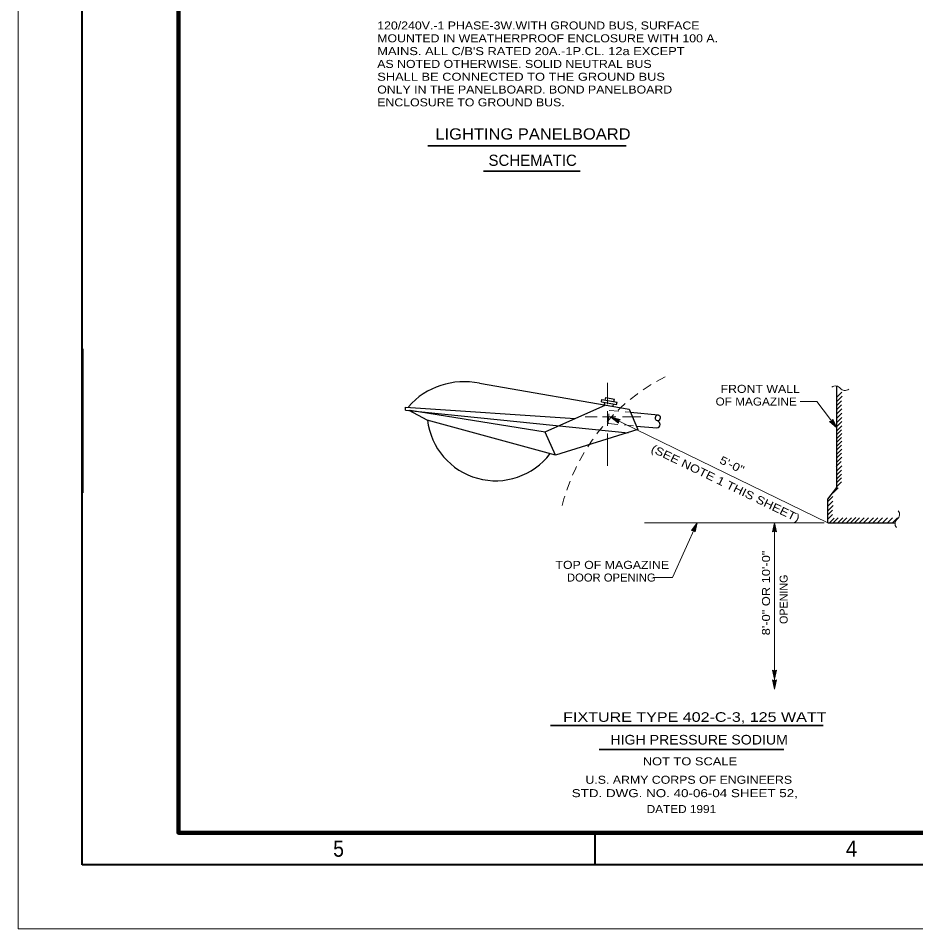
# Model space of a CAD drawing. Extents: x -39.6 to 16.1, y -17.6 to 34.
# Drawn here: x -25.9 to -11.89, y -17.59 to -3.38 of the extents above; entities that cross this region are included whole.
import ezdxf
from ezdxf.enums import TextEntityAlignment as Align

# ---------------------------------------------------------------- set-up
doc = ezdxf.new("R2010")
doc.units = 0
doc.header["$LTSCALE"] = 0.05
doc.linetypes.add('MEDIUM_DASHED', pattern=[4.5, 3, -1.5])
doc.layers.add('1', color=7, linetype='Continuous', lineweight=13)

msp = doc.modelspace()

# ---------------------------------------------------------------- linework, layer by layer
at = {"layer": '1'}
for p, q in [((-25.89821, -17.59158), (-25.89821, 12.40842)), ((-16.69821, -9.40258), (-16.69821, -9.06758)), ((-13.12121, -9.28958), (-13.04321, -9.21158)), ((-13.12321, -9.42758), (-13.04521, -9.34958)), ((-13.11521, -9.35658), (-13.03721, -9.27858)), ((-16.69821, -9.74058), (-16.69821, -9.51058)), ((-13.12321, -9.48858), (-13.04521, -9.41058)), ((-13.12121, -9.55258), (-13.04321, -9.47458)), ((-17.05021, -9.59758), (-16.86121, -9.59758)), ((-16.77721, -9.59758), (-16.57221, -9.59758)), ((-16.64621, -9.60458), (-16.53021, -9.69558)), ((-16.61321, -9.62058), (-16.51921, -9.64358)), ((-16.61321, -9.62058), (-16.53721, -9.67958)), ((-16.58021, -9.63658), (-16.54421, -9.66458)), ((-16.58021, -9.63658), (-16.53621, -9.64758)), ((-16.53621, -9.64758), (-16.54421, -9.65458)), ((-16.54421, -9.65458), (-16.54421, -9.66458)), ((-16.53621, -9.65758), (-16.53721, -9.67958)), ((-16.51921, -9.64358), (-16.53621, -9.65758)), ((-16.46321, -9.59658), (-16.17821, -9.59658)), ((-13.19521, -9.67158), (-13.18521, -9.65258)), ((-13.14321, -9.73958), (-13.18521, -9.65258)), ((-13.12121, -9.76858), (-13.18421, -9.63558)), ((-13.12121, -9.61858), (-13.04321, -9.54058)), ((-13.12121, -9.68758), (-13.04321, -9.60958)), ((-13.12121, -9.76858), (-13.23321, -9.67258)), ((-13.21621, -9.67658), (-13.19521, -9.67158)), ((-13.14321, -9.73958), (-13.21621, -9.67658)), ((-13.20121, -9.68058), (-13.19021, -9.67758)), ((-13.16521, -9.71058), (-13.20121, -9.68058)), ((-13.19021, -9.67758), (-13.18621, -9.66958)), ((-13.16521, -9.71058), (-13.18621, -9.66958)), ((-13.12321, -9.87758), (-13.04521, -9.79958)), ((-13.12121, -9.75058), (-13.04321, -9.67258)), ((-13.12121, -9.81758), (-13.04321, -9.73958)), ((-16.69821, -10.36258), (-16.69821, -9.85658)), ((-13.12321, -9.99758), (-13.04521, -9.91958)), ((-13.12121, -9.93658), (-13.04321, -9.85858)), ((-13.12321, -10.11858), (-13.04521, -10.04058)), ((-13.12121, -10.05558), (-13.04321, -9.97758)), ((-13.12321, -10.24358), (-13.04521, -10.16558)), ((-13.12121, -10.18258), (-13.04321, -10.10458)), ((-13.12121, -10.30658), (-13.04321, -10.22858)), ((-13.12921, -10.37358), (-13.05121, -10.29558)), ((-13.12121, -10.44158), (-13.04321, -10.36358)), ((-13.12321, -10.50858), (-13.04521, -10.43058)), ((-13.12321, -10.56958), (-13.04521, -10.49158)), ((-13.12321, -10.62758), (-13.04521, -10.54958)), ((-13.12321, -10.69058), (-13.04521, -10.61258)), ((-13.17621, -10.78658), (-13.09821, -10.70858)), ((-13.26121, -10.91858), (-13.18321, -10.84058)), ((-13.25821, -10.99258), (-13.18021, -10.91458)), ((-13.26421, -11.13558), (-13.18621, -11.05758)), ((-13.25621, -11.06158), (-13.17821, -10.98358)), ((-13.26421, -11.19958), (-13.18621, -11.12158)), ((-13.24221, -11.26058), (-13.16421, -11.18258)), ((-13.17621, -11.25458), (-13.09821, -11.17658)), ((-13.10521, -11.25258), (-13.02721, -11.17458)), ((-13.04121, -11.25458), (-12.96321, -11.17658)), ((-12.97021, -11.25258), (-12.89221, -11.17458)), ((-12.90121, -11.24658), (-12.82321, -11.16858)), ((-12.84321, -11.25258), (-12.76521, -11.17458)), ((-12.77121, -11.25258), (-12.69321, -11.17458)), ((-12.70221, -11.25258), (-12.62421, -11.17458)), ((-12.62821, -11.25258), (-12.55021, -11.17458)), ((-12.55921, -11.25458), (-12.48121, -11.17658)), ((-12.48521, -11.25258), (-12.40721, -11.17458)), ((-12.40821, -11.25458), (-12.33021, -11.17658)), ((-12.32921, -11.25258), (-12.25121, -11.17458)), ((-12.24921, -11.25258), (-12.17121, -11.17458)), ((-13.31821, -11.25258), (-16.12221, -11.25258)), ((-15.30121, -11.25258), (-15.38821, -11.37158)), ((-15.31621, -11.28658), (-15.37321, -11.36358)), ((-15.35121, -11.36358), (-15.37321, -11.36358)), ((-15.33121, -11.31958), (-15.35821, -11.35658)), ((-15.34821, -11.35658), (-15.35821, -11.35658)), ((-15.33721, -11.38058), (-15.35121, -11.36358)), ((-15.34021, -11.36458), (-15.34821, -11.35658)), ((-15.33121, -11.31958), (-15.34021, -11.36458)), ((-15.31621, -11.28658), (-15.33721, -11.38058)), ((-15.30121, -11.25258), (-15.33221, -11.39658)), ((-14.09121, -11.25258), (-14.12221, -11.39658)), ((-14.09121, -11.28958), (-14.11121, -11.38358)), ((-14.09121, -11.32558), (-14.10021, -11.37058)), ((-14.09121, -11.36658), (-14.10021, -11.37058)), ((-14.09121, -11.25258), (-14.06021, -11.39658)), ((-14.09121, -11.28958), (-14.07121, -11.38358)), ((-14.09121, -11.32558), (-14.08121, -11.37058)), ((-14.08121, -11.37058), (-14.09121, -11.36658)), ((-14.09121, -11.37458), (-14.11121, -11.38358)), ((-14.07121, -11.38358), (-14.09121, -11.37458)), ((-14.09121, -13.69658), (-14.12221, -13.55258)), ((-14.09121, -13.65958), (-14.11121, -13.56558)), ((-14.11121, -13.56558), (-14.09121, -13.57458)), ((-14.09121, -13.62358), (-14.10121, -13.57858)), ((-14.10121, -13.57858), (-14.09121, -13.58258)), ((-14.09121, -13.69658), (-14.06021, -13.55258)), ((-14.09121, -13.65958), (-14.07121, -13.56558)), ((-14.09121, -13.57458), (-14.07121, -13.56558)), ((-14.09121, -13.62358), (-14.08221, -13.57858)), ((-14.09121, -13.58258), (-14.08221, -13.57858)), ((-14.09121, -13.84858), (-14.12221, -13.70458)), ((-14.09121, -13.81158), (-14.11121, -13.71758)), ((-14.11121, -13.71758), (-14.09121, -13.72658)), ((-14.09121, -13.77558), (-14.10121, -13.73058)), ((-14.10121, -13.73058), (-14.09121, -13.73458)), ((-14.09121, -13.84858), (-14.06021, -13.70458)), ((-14.09121, -13.81158), (-14.07121, -13.71758)), ((-14.09121, -13.72658), (-14.07121, -13.71758)), ((-14.09121, -13.77558), (-14.08221, -13.73058)), ((-14.09121, -13.73458), (-14.08221, -13.73058)), ((16.10179, -17.59158), (-25.89821, -17.59158))]:
    msp.add_line(p, q, dxfattribs=at)
at = {"layer": '1', "lineweight": 35}
for p, q in [((-19.50321, -5.36558), (-16.40721, -5.36558)), ((-18.63421, -5.76158), (-17.12521, -5.76158)), ((-17.59021, -14.41858), (-13.33121, -14.41858)), ((-16.82821, -14.79458), (-13.94721, -14.79458))]:
    msp.add_line(p, q, dxfattribs=at)
at = {"layer": '1', "lineweight": 40}
for p, q in [((-24.89721, -8.53658), (-24.89721, -10.78658)), ((-16.89821, -16.09158), (-16.89821, -16.59158))]:
    msp.add_line(p, q, dxfattribs=at)
at = {"layer": '1', "lineweight": 25}
for p, q in [((-18.70021, -9.07558), (-16.36221, -9.47758)), ((-13.12121, -10.70458), (-13.12121, -9.11858)), ((-16.79221, -9.36458), (-16.78621, -9.32858)), ((-16.79221, -9.36458), (-16.55721, -9.40458)), ((-16.78621, -9.32858), (-16.55121, -9.36858)), ((-16.74721, -9.41158), (-16.74121, -9.37358)), ((-16.73521, -9.33758), (-16.72821, -9.29758)), ((-16.72821, -9.29758), (-16.59321, -9.32058)), ((-16.60021, -9.36058), (-16.59321, -9.32058)), ((-16.55721, -9.40458), (-16.55121, -9.36858)), ((-19.85121, -9.44658), (-17.20721, -9.62458)), ((-19.85121, -9.49258), (-19.85121, -9.44658)), ((-19.85121, -9.49258), (-16.37521, -9.84958)), ((-16.73021, -9.41458), (-17.67821, -9.83658)), ((-16.61221, -9.43458), (-16.60621, -9.39558)), ((-16.34321, -9.52658), (-15.91021, -9.56558)), ((-16.24621, -9.74358), (-15.92821, -9.77158)), ((-13.26121, -10.88458), (-13.12121, -10.70458)), ((-13.26121, -11.25258), (-13.26121, -10.88458)), ((-13.26121, -11.25258), (-12.21021, -11.25258))]:
    msp.add_line(p, q, dxfattribs=at)
at = {"layer": '1', "linetype": 'MEDIUM_DASHED'}
for p, q in [((-16.68821, -9.70358), (-16.67221, -9.49758)), ((-16.67221, -9.49758), (-16.34321, -9.52658)), ((-16.69021, -9.70358), (-16.25421, -9.74258))]:
    msp.add_line(p, q, dxfattribs=at)
at = {"layer": '1', "lineweight": 40}
msp.add_lwpolyline([(-24.89821, -16.59158), (-24.89821, 11.40842), (15.10179, 11.40842), (15.10179, -16.59158)], close=True, dxfattribs=at)
at = {"layer": '1', "lineweight": 90}
msp.add_lwpolyline([(-23.39821, 10.90842), (14.60179, 10.90842), (14.60179, -16.09158), (-23.39821, -16.09158)], close=True, dxfattribs=at)
at = {"layer": '1'}
for points in [[(-13.12121, -9.76858), (-13.43321, -9.36058), (-13.69121, -9.36058)], [(-13.26121, -11.25258), (-16.64621, -9.60458), (-16.50321, -9.63958)], [(-16.50321, -9.63958), (-16.52921, -9.66158), (-16.53021, -9.69558)], [(-13.23321, -9.67258), (-13.20021, -9.66558), (-13.18421, -9.63558)], [(-15.30121, -11.25258), (-15.68721, -12.10858), (-15.98921, -12.10858)], [(-15.33221, -11.39658), (-15.35421, -11.37158), (-15.38821, -11.37158)], [(-14.09121, -11.25258), (-14.09121, -13.69658), (-14.09121, -13.84858)], [(-14.06021, -11.39658), (-14.09121, -11.38258), (-14.12221, -11.39658)], [(-14.12221, -13.55258), (-14.09121, -13.56658), (-14.06021, -13.55258)], [(-14.12221, -13.70458), (-14.09121, -13.71858), (-14.06021, -13.70458)]]:
    msp.add_lwpolyline(points, dxfattribs=at)
at = {"layer": '1', "lineweight": 25}
for points in [[(-16.36221, -9.47758), (-16.22521, -9.79658), (-17.51221, -10.19658), (-19.51521, -9.64858), (-19.79721, -9.49858)], [(-17.51221, -10.19658), (-17.67521, -9.83558), (-19.78021, -9.49958)]]:
    msp.add_lwpolyline(points, dxfattribs=at)
for centre, radius, start, end in [((-18.93988, -10.2099), 1.15936, 78.06949, 138.42735), ((-18.44693, -9.5268), 1.06947, 186.64632, 322.78773), ((-15.93552, -9.71675), 0.05532, 277.59372, 73.93349)]:
    msp.add_arc(centre, radius, start, end, dxfattribs=at)
at = {"layer": '1', "linetype": 'MEDIUM_DASHED'}
msp.add_arc((-14.36887, -11.76436), 3.13823, 117.17653, 166.72192, dxfattribs=at)
at = {"layer": '1'}
for centre, start, end in [((-13.13901, -9.20887), 37.70802, 129.22771), ((-12.9934, -9.0963), 217.70802, 309.22771), ((-12.23249, -11.12278), 307.70802, 39.22771), ((-12.11992, -11.26839), 127.70802, 219.22771)]:
    msp.add_arc(centre, 0.09202, start, end, dxfattribs=at)
at = {"layer": '1', "lineweight": 25}
msp.add_ellipse((-15.91571, -9.61458), major_axis=(-0.0055, -0.049), ratio=0.757637, dxfattribs=at)

# ---------------------------------------------------------------- texts
at = {"layer": '1'}
for s, width, p in [('120/240V.-1 PHASE-3W.WITH GROUND BUS, SURFACE', 1.15, (-20.29421, -3.55158)), ('MOUNTED IN WEATHERPROOF ENCLOSURE WITH 100 A.', 1.15, (-20.29421, -3.75158)), ("MAINS. ALL C/B'S RATED 20A.-1P.CL. 12a EXCEPT", 1.2, (-20.29421, -3.95158)), ('AS NOTED OTHERWISE. SOLID NEUTRAL BUS', 1.15, (-20.29421, -4.15158)), ('SHALL BE CONNECTED TO THE GROUND BUS', 1.2, (-20.29421, -4.35158)), ('ONLY IN THE PANELBOARD. BOND PANELBOARD', 1.15, (-20.29421, -4.55158)), ('ENCLOSURE TO GROUND BUS.', 1.15, (-20.29421, -4.75158))]:
    msp.add_text(s, height=0.125, dxfattribs=dict(at, width=width)).set_placement(p)
for s, height, width, p in [('LIGHTING PANELBOARD', 0.175, 1.1, (-17.86321, -5.26958)), ('FRONT WALL', 0.125, 1.15, (-14.31621, -9.22458)), ('TOP OF MAGAZINE', 0.125, 1.15, (-16.62571, -11.97258)), ('FIXTURE TYPE 402-C-3, 125 WATT', 0.15, 1.25, (-15.33671, -14.36058)), ('HIGH PRESSURE SODIUM', 0.15, 1.1, (-15.26971, -14.71458)), ('NOT TO SCALE', 0.125, 1.2, (-15.41321, -15.03958)), ('U.S. ARMY CORPS OF ENGINEERS', 0.125, 1.15, (-15.43121, -15.32758)), ('STD. DWG. NO. 40-06-04 SHEET 52,', 0.125, 1.25, (-15.49321, -15.53658)), ('DATED 1991', 0.125, 1.1, (-15.54621, -15.78458)), ('5', 0.25, 0.9, (-20.89771, -16.46658)), ('4', 0.25, 0.95, (-12.89171, -16.46658))]:
    msp.add_text(s, height=height, dxfattribs=dict(at, width=width)).set_placement(p, align=Align.CENTER)
msp.add_text('SCHEMATIC', height=0.175, dxfattribs=at).set_placement((-17.86821, -5.68058), align=Align.CENTER)
for s, width, p in [('OF MAGAZINE', 1.1, (-13.74621, -9.42258)), ('DOOR OPENING', 1.05, (-15.94821, -12.17058))]:
    msp.add_text(s, height=0.125, dxfattribs=dict(at, width=width)).set_placement(p, align=Align.RIGHT)
at = {"layer": '1', "width": 1.2}
for s, rotation, p in [('(SEE NOTE 1 THIS SHEET)', 334.201, (-14.8843, -10.6938)), ('5\'-0"', 334.201, (-14.78363, -10.40453)), ('8\'-0" OR 10\'-0"', 90, (-14.16321, -12.34858))]:
    msp.add_text(s, height=0.125, rotation=rotation, dxfattribs=at).set_placement(p, align=Align.CENTER)
at = {"layer": '1'}
msp.add_text('OPENING', height=0.125, rotation=90, dxfattribs=at).set_placement((-13.88821, -12.44708), align=Align.CENTER)

doc.saveas('drawing.dxf')
